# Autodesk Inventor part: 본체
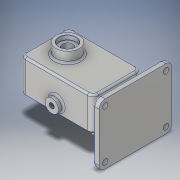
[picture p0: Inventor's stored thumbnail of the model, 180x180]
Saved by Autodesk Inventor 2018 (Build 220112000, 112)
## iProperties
Created: 2020-04
Part Number: 본체
Material: 알루미늄 6061
Document SubType Name: Modeling
Designer: 1class 18
Density: 2.7 g/cm^3
Appearance: 알루미늄 - 평지
Mass: 1472.54 g
Surface Area: 818.391 cm^2
Volume: 545.387 cm^3
Author: 1class 18
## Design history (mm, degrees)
node "주석"
  node "선형 치수 1" dims "d100" = 62 (derived)
sketch "스케치1"
  geometry: 1 further point
sketch "스케치2"
  geometry: L1 (0, 0)-(120, 0); L2 (120, 0)-(120, -80); L3 (120, -80)-(0, -80); L4 (0, -80)-(0, 0); L5 (82, -16)-(38, -16); L6 (38, -64)-(82, -64); A1 r 24 centre (82, -40) between (82, -64) and (82, -16); A2 r 24 centre (38, -40) between (38, -16) and (38, -64)
  constraints: 12 end point, 4 point on circle, 3 parallel, 2 centre point, 2 horizontal, 2 tangent, 1 perpendicular
  dimensions: "d0" = 120 distance of L2.end L3.end; "d1" = 80 distance of L1.end L2.end; "d2" = 48 diameter of A1; "d3" = 48 diameter of A2; "d4" = 44 distance of A2.centre A1.centre; "d5" = 40 distance from line of L1 A1.centre; "d6" = 38 distance from line of L2 A1.centre
extrude "돌출1" new body sketch "스케치2" distance "d7" = 53; taper "d8" = 0 deg
sketch "스케치3"
  geometry: L1 (-120, 0)-(0, 0) reference; L2 (-120, 80)-(-120, 0) reference; C1 r 12.5 at (-82, 40); C2 r 12.5 at (-38, 40)
  constraints: 2 centre point, 1 horizontal alignment
  dimensions: "d9" = 25 diameter of C1; "d10" = 25 diameter of C2; "d11" = 40 distance from line of L1 C1.centre; "d12" = 38 distance from line of L2 C1.centre; "d13" = 44 distance of C1.centre C2.centre
extrude "돌출2" join sketch "스케치2" distance "d14" = 53; taper "d15" = 0 deg
extrude "돌출3" cut sketch "스케치2" distance "d16" = 29; taper "d17" = 0 deg
sketch "스케치4"
  geometry: L1 (-120, 0)-(-120, -80) reference; L2 (-120, -80)-(0, -80) reference; C1 r 12.5 at (-38, -40); C2 r 12.5 at (-82, -40); 1 further point
  constraints: 2 centre point, 1 horizontal alignment
  dimensions: "d18" = 25 diameter of C1; "d19" = 25 diameter of C2; "d20" = 38 distance from line of L1 C2.centre; "d21" = 40 distance from line of L2 C2.centre; "d22" = 44 distance of C2.centre C1.centre
extrude "돌출4" cut sketch "스케치4" distance "d23" = 15; taper "d24" = 0 deg
sketch "스케치5"
  geometry: C1 r 12.5 at (-82, 40) reference; C2 r 19 at (-82, 40); 1 further point
  constraints: 1 centre point, 1 coincident
  dimensions: "d25" = 38 diameter of C2
extrude "돌출5" join sketch "스케치5" distance "d26" = 17; taper "d27" = 0 deg
sketch "스케치6"
  geometry: C1 r 14 at (0, 0); 1 further point
  constraints: 1 centre point
  dimensions: "d28" = 28 diameter of C1
extrude "돌출6" cut sketch "스케치6" distance "d29" = 7.3; taper "d30" = 0 deg
sketch "스케치7"
  geometry: C1 r 8.5 at (0, 0); 1 further point
  constraints: 1 centre point
  dimensions: "d31" = 17 diameter of C1
extrude "돌출7" cut sketch "스케치7" extent not by distance; stored distance "d32" = 7.3; taper "d33" = 0 deg
node "작업 평면1"
sketch "스케치8"
  geometry: L1 (-30, -100)-(70, -100); L2 (70, -100)-(70, 20); L3 (70, 20)-(-30, 20); L4 (-30, 20)-(-30, -100); L5 (70, -59)-(70, -21) reference; L6 (0, -80)-(53, -80) reference; 1 further point
  constraints: 8 end point, 2 parallel, 1 horizontal, 1 perpendicular
  dimensions: "d35" = 100 distance of L3.end L2.end; "d36" = 120 distance of L2.end L1.end; "d37" = 0 distance between parallel lines of L5 L2; "d38" = 20 distance between parallel lines of L6 L1
extrude "돌출8" join sketch "스케치8" distance "d39" = 10; taper "d40" = 0 deg
node "작업 평면2"
sketch "스케치9"
  geometry: L1 (20, 70)-(20, -30) reference; L2 (0, 0)-(-120, 0) reference; L3 (0, 0)-(0, 53) reference; L4 (-120, 53)-(0, 53) reference; L5 (30, 70)-(30, -30) reference; L6 (20, -30)-(20, 70) reference; L7 (30, 70)-(20, 70) reference; L8 (20, 0)-(-3.153, 13.367); L9 (0, 0)-(0, 53) reference; L10 (20, 0)-(43.094, 0); L11 (20, 53)-(-3.153, 39.633); L12 (20, 53)-(48.512, 53); L13 (-3.153, 39.633)-(-3.153, 13.367); L14 (20, 0)-(20, 53)
  constraints: 12 end point, 2 horizontal, 2 point on line, 1 collinear, 1 vertical
  dimensions: "d42" = 17 distance from line of L7 L11.start; "d43" = 53 distance of L8.start L11.start; "d44" = 150 deg angle of L10 L8; "d45" = 150 deg angle of L11 L12
extrude "돌출9" join sketch "스케치9" stored distance "d46" = 48; taper "d47" = 0 deg
sketch "스케치10"
  geometry: L1 (-120, -80)-(0, -80) reference; L2 (-120, 0)-(-120, -80) reference; L3 (-120, -40)-(0, -40); L4 (0, 0)-(0, -80) reference; 8 further points
  constraints: 4 symmetric about line, 3 horizontal alignment, 2 end point, 2 midpoint
  dimensions: "d48" = 9 distance from line of L1 point (-111, -71); "d49" = 9 distance from line of L2 point (-111, -71); "d50" = 29 distance of point (-111, -71) point (-82, -71); "d51" = 44 distance of point (-38, -71) point (-82, -71); "d52" = 29 distance of point (-38, -71) point (-9, -71)
hole "구멍1" sketch "스케치10" at (-111, -71), (-82, -71), (-38, -71), (-9, -71), (-9, -9), (-38, -9), (-82, -9), (-111, -9) diameter "d53" = 4.134; stored, may be unused: countersink angle "d57" = 90 deg, drill point angle "d59" = 118 deg; dims "d54" = 10, "d55" = 4, "d56" = 2, "d58" = 12
sketch "스케치11"
  geometry: L1 (120, 0)-(0, 0) reference; L2 (120, 0)-(120, 53) reference; C1 r 11 at (60, 14)
  constraints: 1 centre point
  dimensions: "d60" = 22 diameter of C1; "d61" = 14 distance from line of L1 C1.centre; "d62" = 60 distance from line of L2 C1.centre
extrude "돌출10" join sketch "스케치11" distance "d63" = 8; taper "d64" = 0 deg
sketch "스케치12"
  geometry: 2 further points
hole "구멍2" sketch "스케치12" at (0, 0) diameter "d65" = 8.376; stored, may be unused: countersink angle "d69" = 90 deg, drill point angle "d71" = 118 deg; dims "d66" = 27, "d67" = 4, "d68" = 2, "d70" = 27.3
node "작업 평면3"
fillet "모깎기1" dims "d73" = 3
fillet "모깎기2" dims "d74" = 3
sketch "스케치13"
  geometry: L1 (20, 70)-(-100, 70) reference; L2 (-100, 70)-(-100, -30) reference; L3 (-40, 70)-(-40, -30); L4 (-100, -30)-(20, -30) reference; L5 (-100, 20)-(20, 20); C1 r 4.5 at (-90, 60); C2 r 4.5 at (-90, -20); C3 r 4.5 at (10, 60); C4 r 4.5 at (10, -20); 1 further point
  constraints: 4 centre point, 4 end point, 3 midpoint, 3 symmetric about line, 1 horizontal, 3 other
  dimensions: "d75" = 9 diameter of C1; "d76" = 10 distance from line of L1 C1.centre; "d77" = 10 distance from line of L2 C1.centre
extrude "돌출11" cut sketch "스케치13" distance "d78" = 10; taper "d79" = 0 deg
sketch "스케치14"
  geometry: L1 (-100, 70)-(-100, -30) reference; L2 (-100, -30)-(20, -30) reference; 2 further points
  constraints: 1 other
  dimensions: "d80" = 60 distance from line of L1 point (-40, -20); "d81" = 10 distance from line of L2 point (-40, -20)
extrude "돌출12" join sketch "스케치14" distance "d82" = 0.5; taper "d83" = 0 deg
fillet "모깎기3" dims "d84" = 10
fillet "모깎기4" dims "d85" = 3
fillet "모깎기5" dims "d86" = 9
fillet "모깎기6" dims "d87" = 3
fillet "모깎기7" dims "d88" = 3
fillet "모깎기8" dims "d92" = 0.5
chamfer "모따기2" distance "d93" = 1; stored, may be unused: second distance "d94" = 2, angle "d95" = 30 deg
fillet "모깎기9" dims "d96" = 3
fillet "모깎기10" dims "d97" = 3
chamfer "모따기3" distance "d101" = 0.7; stored, may be unused: second distance "d102" = 2, angle "d103" = 30 deg
node "솔리드1"
mirror "미러1"
other parameters: "d98" = 6.49151 (derived), "d99" = 4.54171 (derived)
